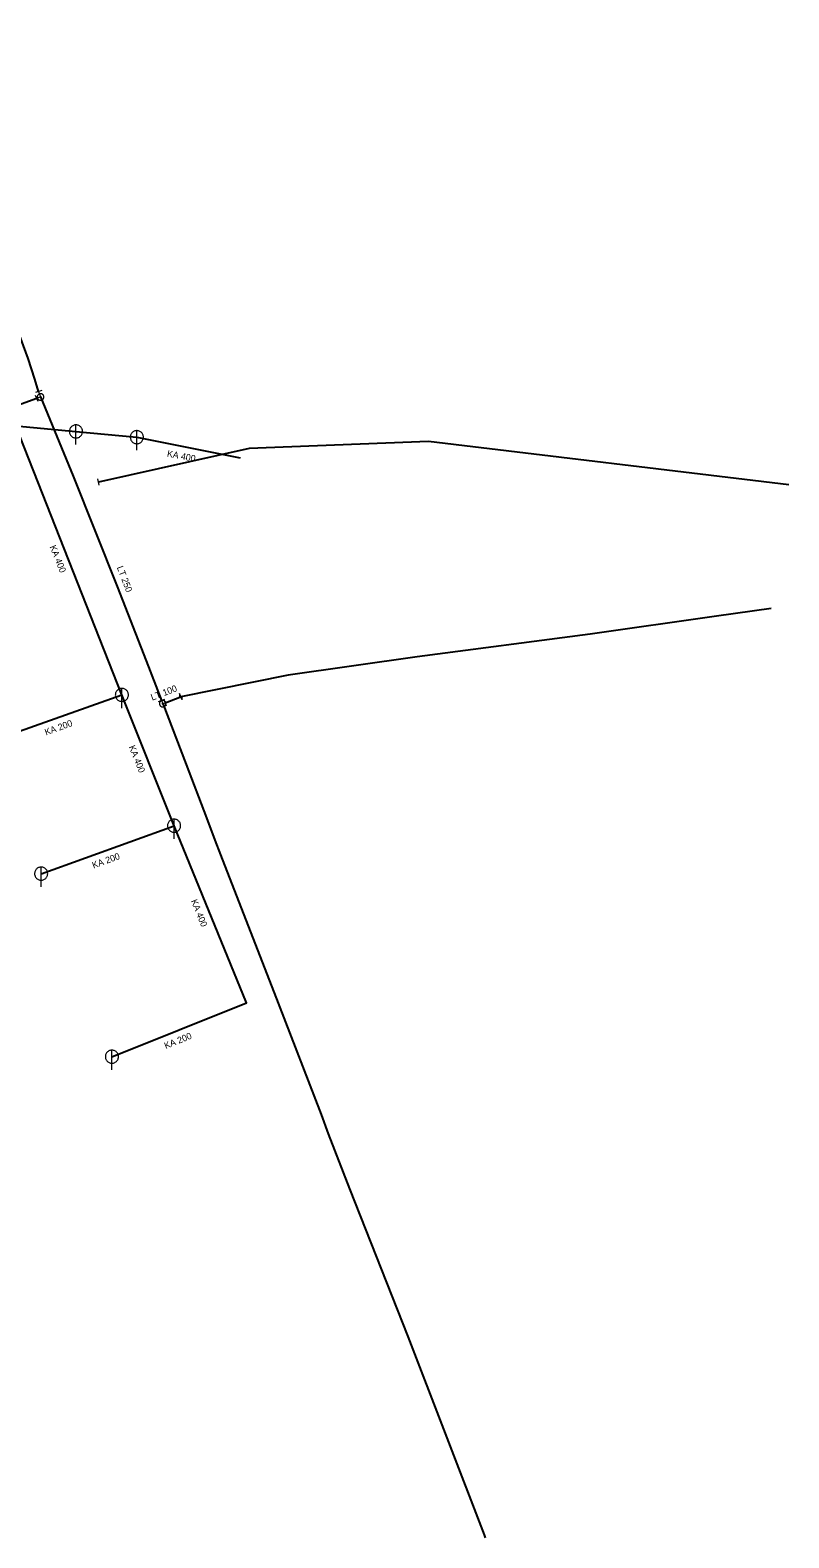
# Model space of a CAD drawing. Extents: x -690535 to -689974, y -975624 to -975325.
# Drawn here: x -690089.9 to -689974.2, y -975566.6 to -975336.7 of the extents above; entities that cross this region are included whole.
import ezdxf

# ---------------------------------------------------------------- set-up
doc = ezdxf.new("R2010")
doc.units = 0
doc.header["$LTSCALE"] = 0.4
for name, color, linetype, lineweight in [('1', 7, 'Continuous', 13), ('14', 7, 'Continuous', 25), ('17', 7, 'Continuous', 25), ('22', 7, 'Continuous', 13), ('34', 7, 'Continuous', 13), ('47', 7, 'Continuous', 13)]:
    doc.layers.add(name, color=color, linetype=linetype, lineweight=lineweight)

msp = doc.modelspace()

# ---------------------------------------------------------------- linework, layer by layer
at = {"layer": '14', "lineweight": 13}
for p, q in [((-690088.342, -975392.645), (-690088.912, -975392.874)), ((-690088.634, -975391.824), (-690088.342, -975392.645))]:
    msp.add_line(p, q, dxfattribs=at)
at = {"layer": '14'}
for p, q in [((-690092.12, -975397.03), (-690082.941, -975397.9)), ((-690082.941, -975397.9), (-690073.66, -975398.78)), ((-690073.66, -975398.78), (-690057.912, -975401.947))]:
    msp.add_line(p, q, dxfattribs=at)
for points in [[(-690094.732, -975444.739), (-690075.94, -975438.079), (-690092.12, -975397.03)], [(-690088.254, -975465.344), (-690067.978, -975458.03), (-690075.94, -975438.079)], [(-690077.458, -975493.256), (-690056.94, -975485.02), (-690067.978, -975458.03)]]:
    msp.add_lwpolyline(points, dxfattribs=at)
at = {"layer": '14', "lineweight": 13}
msp.add_lwpolyline([(-690069.916, -975438.943), (-690069.713, -975439.412), (-690069.351, -975439.267)], dxfattribs=at)
at = {"layer": '17'}
msp.add_line((-690088.912, -975392.874), (-690093.531, -975394.548), dxfattribs=at)
for points in [[(-690088.634, -975391.824), (-690089.23, -975389.914), (-690090.217, -975386.78), (-690091.866, -975382.373), (-690092.267, -975381.329), (-690094.342, -975375.603), (-690098.616, -975364.307), (-690100.726, -975358.546), (-690108.436, -975337.406), (-690108.682, -975336.702)], [(-690088.342, -975392.645), (-690083.348, -975404.702), (-690076.64, -975421.557), (-690072.237, -975432.873), (-690069.916, -975438.943)], [(-689974.23, -975406.039), (-690029.157, -975399.432), (-690056.529, -975400.526), (-690079.517, -975405.619)], [(-689976.911, -975424.893), (-689985.28, -975426.09), (-690004.51, -975428.82), (-690030.89, -975432.25), (-690050.579, -975435.05), (-690066.965, -975438.351)], [(-690069.713, -975439.412), (-690066.124, -975448.715), (-690063.059, -975456.824), (-690061.761, -975460.213), (-690060.916, -975462.471), (-690052.092, -975485.109), (-690045.574, -975502.066), (-690044.477, -975505.021), (-690041.228, -975513.396), (-690032.318, -975535.925), (-690020.684, -975566.182), (-690020.552, -975566.636)], [(-690069.351, -975439.267), (-690067.107, -975438.425), (-690066.965, -975438.351)]]:
    msp.add_lwpolyline(points, dxfattribs=at)
at = {"layer": '22'}
for p, q in [((-690082.941, -975399.9), (-690082.94, -975396.9)), ((-690073.66, -975400.78), (-690073.659, -975397.78)), ((-690075.94, -975440.079), (-690075.939, -975437.079)), ((-690067.978, -975460.03), (-690067.977, -975457.03)), ((-690088.254, -975467.344), (-690088.253, -975464.344)), ((-690077.458, -975495.256), (-690077.457, -975492.256))]:
    msp.add_line(p, q, dxfattribs=at)
for points in [[(-690081.941, -975397.9), (-690081.946, -975397.791), (-690081.964, -975397.683), (-690081.994, -975397.577), (-690082.034, -975397.476), (-690082.086, -975397.379), (-690082.148, -975397.289), (-690082.22, -975397.206), (-690082.3, -975397.132), (-690082.388, -975397.066), (-690082.482, -975397.011), (-690082.582, -975396.966), (-690082.687, -975396.933), (-690082.794, -975396.911), (-690082.903, -975396.901), (-690083.013, -975396.903), (-690083.121, -975396.917), (-690083.228, -975396.942), (-690083.331, -975396.979), (-690083.429, -975397.028), (-690083.521, -975397.086), (-690083.607, -975397.155), (-690083.684, -975397.232), (-690083.753, -975397.318), (-690083.812, -975397.41), (-690083.86, -975397.508), (-690083.897, -975397.611), (-690083.923, -975397.718), (-690083.937, -975397.826), (-690083.94, -975397.936), (-690083.93, -975398.045), (-690083.909, -975398.152), (-690083.875, -975398.256), (-690083.831, -975398.356), (-690083.776, -975398.451), (-690083.71, -975398.539), (-690083.636, -975398.619), (-690083.553, -975398.691), (-690083.463, -975398.753), (-690083.367, -975398.805), (-690083.265, -975398.846), (-690083.16, -975398.876), (-690083.052, -975398.894), (-690082.942, -975398.9), (-690082.833, -975398.894), (-690082.725, -975398.876), (-690082.62, -975398.847), (-690082.518, -975398.806), (-690082.421, -975398.754), (-690082.331, -975398.692), (-690082.248, -975398.621), (-690082.173, -975398.541), (-690082.108, -975398.453), (-690082.052, -975398.359), (-690082.008, -975398.259), (-690081.974, -975398.155), (-690081.952, -975398.047), (-690081.942, -975397.938)], [(-690072.66, -975398.78), (-690072.665, -975398.671), (-690072.683, -975398.563), (-690072.713, -975398.457), (-690072.753, -975398.356), (-690072.805, -975398.259), (-690072.867, -975398.169), (-690072.939, -975398.086), (-690073.019, -975398.012), (-690073.107, -975397.946), (-690073.201, -975397.891), (-690073.301, -975397.846), (-690073.406, -975397.813), (-690073.513, -975397.791), (-690073.622, -975397.781), (-690073.732, -975397.783), (-690073.84, -975397.797), (-690073.947, -975397.822), (-690074.05, -975397.859), (-690074.148, -975397.908), (-690074.24, -975397.966), (-690074.326, -975398.035), (-690074.403, -975398.112), (-690074.472, -975398.198), (-690074.531, -975398.29), (-690074.579, -975398.388), (-690074.616, -975398.491), (-690074.642, -975398.598), (-690074.656, -975398.706), (-690074.659, -975398.816), (-690074.649, -975398.925), (-690074.628, -975399.032), (-690074.594, -975399.136), (-690074.55, -975399.236), (-690074.495, -975399.331), (-690074.429, -975399.419), (-690074.355, -975399.499), (-690074.272, -975399.571), (-690074.182, -975399.633), (-690074.086, -975399.685), (-690073.984, -975399.726), (-690073.879, -975399.756), (-690073.771, -975399.774), (-690073.661, -975399.78), (-690073.552, -975399.774), (-690073.444, -975399.756), (-690073.339, -975399.727), (-690073.237, -975399.686), (-690073.14, -975399.634), (-690073.05, -975399.572), (-690072.967, -975399.501), (-690072.892, -975399.421), (-690072.827, -975399.333), (-690072.771, -975399.239), (-690072.727, -975399.139), (-690072.693, -975399.035), (-690072.671, -975398.927), (-690072.661, -975398.818)], [(-690074.94, -975438.079), (-690074.945, -975437.97), (-690074.963, -975437.862), (-690074.993, -975437.756), (-690075.033, -975437.655), (-690075.085, -975437.558), (-690075.147, -975437.468), (-690075.219, -975437.385), (-690075.299, -975437.311), (-690075.387, -975437.245), (-690075.481, -975437.19), (-690075.581, -975437.145), (-690075.686, -975437.112), (-690075.793, -975437.09), (-690075.902, -975437.08), (-690076.012, -975437.082), (-690076.12, -975437.096), (-690076.227, -975437.121), (-690076.33, -975437.158), (-690076.428, -975437.207), (-690076.52, -975437.265), (-690076.606, -975437.334), (-690076.683, -975437.411), (-690076.752, -975437.497), (-690076.811, -975437.589), (-690076.859, -975437.687), (-690076.896, -975437.79), (-690076.922, -975437.897), (-690076.936, -975438.005), (-690076.939, -975438.115), (-690076.929, -975438.224), (-690076.908, -975438.331), (-690076.874, -975438.435), (-690076.83, -975438.535), (-690076.775, -975438.63), (-690076.709, -975438.718), (-690076.635, -975438.798), (-690076.552, -975438.87), (-690076.462, -975438.932), (-690076.366, -975438.984), (-690076.264, -975439.025), (-690076.159, -975439.055), (-690076.051, -975439.073), (-690075.941, -975439.079), (-690075.832, -975439.073), (-690075.724, -975439.055), (-690075.619, -975439.026), (-690075.517, -975438.985), (-690075.42, -975438.933), (-690075.33, -975438.871), (-690075.247, -975438.8), (-690075.172, -975438.72), (-690075.107, -975438.632), (-690075.051, -975438.538), (-690075.007, -975438.438), (-690074.973, -975438.334), (-690074.951, -975438.226), (-690074.941, -975438.117)], [(-690066.978, -975458.03), (-690066.983, -975457.921), (-690067.001, -975457.813), (-690067.031, -975457.707), (-690067.071, -975457.606), (-690067.123, -975457.509), (-690067.185, -975457.419), (-690067.257, -975457.336), (-690067.337, -975457.262), (-690067.425, -975457.196), (-690067.519, -975457.141), (-690067.619, -975457.096), (-690067.724, -975457.063), (-690067.831, -975457.041), (-690067.94, -975457.031), (-690068.05, -975457.033), (-690068.158, -975457.047), (-690068.265, -975457.072), (-690068.368, -975457.109), (-690068.466, -975457.158), (-690068.558, -975457.216), (-690068.644, -975457.285), (-690068.721, -975457.362), (-690068.79, -975457.448), (-690068.849, -975457.54), (-690068.897, -975457.638), (-690068.934, -975457.741), (-690068.96, -975457.848), (-690068.974, -975457.956), (-690068.977, -975458.066), (-690068.967, -975458.175), (-690068.946, -975458.282), (-690068.912, -975458.386), (-690068.868, -975458.486), (-690068.813, -975458.581), (-690068.747, -975458.669), (-690068.673, -975458.749), (-690068.59, -975458.821), (-690068.5, -975458.883), (-690068.404, -975458.935), (-690068.302, -975458.976), (-690068.197, -975459.006), (-690068.089, -975459.024), (-690067.979, -975459.03), (-690067.87, -975459.024), (-690067.762, -975459.006), (-690067.657, -975458.977), (-690067.555, -975458.936), (-690067.458, -975458.884), (-690067.368, -975458.822), (-690067.285, -975458.751), (-690067.21, -975458.671), (-690067.145, -975458.583), (-690067.089, -975458.489), (-690067.045, -975458.389), (-690067.011, -975458.285), (-690066.989, -975458.177), (-690066.979, -975458.068)], [(-690087.254, -975465.344), (-690087.259, -975465.235), (-690087.277, -975465.127), (-690087.307, -975465.021), (-690087.347, -975464.92), (-690087.399, -975464.823), (-690087.461, -975464.733), (-690087.533, -975464.65), (-690087.613, -975464.576), (-690087.701, -975464.51), (-690087.795, -975464.455), (-690087.895, -975464.41), (-690088, -975464.377), (-690088.107, -975464.355), (-690088.216, -975464.345), (-690088.326, -975464.347), (-690088.434, -975464.361), (-690088.541, -975464.386), (-690088.644, -975464.423), (-690088.742, -975464.472), (-690088.834, -975464.53), (-690088.92, -975464.599), (-690088.997, -975464.676), (-690089.066, -975464.762), (-690089.125, -975464.854), (-690089.173, -975464.952), (-690089.21, -975465.055), (-690089.236, -975465.162), (-690089.25, -975465.27), (-690089.253, -975465.38), (-690089.243, -975465.489), (-690089.222, -975465.596), (-690089.188, -975465.7), (-690089.144, -975465.8), (-690089.089, -975465.895), (-690089.023, -975465.983), (-690088.949, -975466.063), (-690088.866, -975466.135), (-690088.776, -975466.197), (-690088.68, -975466.249), (-690088.578, -975466.29), (-690088.473, -975466.32), (-690088.365, -975466.338), (-690088.255, -975466.344), (-690088.146, -975466.338), (-690088.038, -975466.32), (-690087.933, -975466.291), (-690087.831, -975466.25), (-690087.734, -975466.198), (-690087.644, -975466.136), (-690087.561, -975466.065), (-690087.486, -975465.985), (-690087.421, -975465.897), (-690087.365, -975465.803), (-690087.321, -975465.703), (-690087.287, -975465.599), (-690087.265, -975465.491), (-690087.255, -975465.382)], [(-690076.458, -975493.256), (-690076.463, -975493.147), (-690076.481, -975493.039), (-690076.511, -975492.933), (-690076.551, -975492.832), (-690076.603, -975492.735), (-690076.665, -975492.645), (-690076.737, -975492.562), (-690076.817, -975492.488), (-690076.905, -975492.422), (-690076.999, -975492.367), (-690077.099, -975492.322), (-690077.204, -975492.289), (-690077.311, -975492.267), (-690077.42, -975492.257), (-690077.53, -975492.259), (-690077.638, -975492.273), (-690077.745, -975492.298), (-690077.848, -975492.335), (-690077.946, -975492.384), (-690078.038, -975492.442), (-690078.124, -975492.511), (-690078.201, -975492.588), (-690078.27, -975492.674), (-690078.329, -975492.766), (-690078.377, -975492.864), (-690078.414, -975492.967), (-690078.44, -975493.074), (-690078.454, -975493.182), (-690078.457, -975493.292), (-690078.447, -975493.401), (-690078.426, -975493.508), (-690078.392, -975493.612), (-690078.348, -975493.712), (-690078.293, -975493.807), (-690078.227, -975493.895), (-690078.153, -975493.975), (-690078.07, -975494.047), (-690077.98, -975494.109), (-690077.884, -975494.161), (-690077.782, -975494.202), (-690077.677, -975494.232), (-690077.569, -975494.25), (-690077.459, -975494.256), (-690077.35, -975494.25), (-690077.242, -975494.232), (-690077.137, -975494.203), (-690077.035, -975494.162), (-690076.938, -975494.11), (-690076.848, -975494.048), (-690076.765, -975493.977), (-690076.69, -975493.897), (-690076.625, -975493.809), (-690076.569, -975493.715), (-690076.525, -975493.615), (-690076.491, -975493.511), (-690076.469, -975493.403), (-690076.459, -975493.294)]]:
    msp.add_lwpolyline(points, close=True, dxfattribs=at)
at = {"layer": '34'}
for p, q in [((-690088.156, -975391.674), (-690089.111, -975391.972)), ((-690088.725, -975393.337), (-690089.097, -975392.409)), ((-690079.408, -975406.107), (-690079.624, -975405.13)), ((-690069.449, -975438.763), (-690070.383, -975439.121)), ((-690069.537, -975438.803), (-690069.165, -975439.731))]:
    msp.add_line(p, q, dxfattribs=at)
at = {"layer": '47'}
msp.add_line((-690066.77, -975438.821), (-690066.767, -975438.311), dxfattribs=at)
for points in [[(-690088.174, -975393.116), (-690088.126, -975393.096), (-690088.08, -975393.071), (-690088.038, -975393.041), (-690087.997, -975393.007), (-690087.961, -975392.969), (-690087.929, -975392.927), (-690087.903, -975392.883), (-690087.88, -975392.835), (-690087.862, -975392.787), (-690087.85, -975392.735), (-690087.843, -975392.683), (-690087.842, -975392.631), (-690087.846, -975392.579), (-690087.856, -975392.527), (-690087.87, -975392.477), (-690087.89, -975392.429), (-690087.915, -975392.383), (-690087.946, -975392.34), (-690087.979, -975392.3), (-690088.017, -975392.264), (-690088.059, -975392.232), (-690088.104, -975392.205), (-690088.151, -975392.182), (-690088.2, -975392.165), (-690088.251, -975392.153), (-690088.303, -975392.146), (-690088.355, -975392.144), (-690088.407, -975392.149), (-690088.459, -975392.159), (-690088.509, -975392.173), (-690088.557, -975392.193), (-690088.603, -975392.218), (-690088.647, -975392.248), (-690088.686, -975392.282), (-690088.722, -975392.32), (-690088.754, -975392.361), (-690088.782, -975392.406), (-690088.804, -975392.453), (-690088.821, -975392.503), (-690088.833, -975392.554), (-690088.84, -975392.606), (-690088.842, -975392.657), (-690088.837, -975392.71), (-690088.827, -975392.762), (-690088.813, -975392.812), (-690088.793, -975392.86), (-690088.768, -975392.906), (-690088.739, -975392.949), (-690088.704, -975392.989), (-690088.666, -975393.025), (-690088.625, -975393.057), (-690088.581, -975393.084), (-690088.533, -975393.106), (-690088.484, -975393.124), (-690088.432, -975393.136), (-690088.38, -975393.143), (-690088.329, -975393.144), (-690088.276, -975393.14), (-690088.224, -975393.13)], [(-690088.314, -975392.722), (-690088.306, -975392.719), (-690088.299, -975392.714), (-690088.292, -975392.71), (-690088.285, -975392.704), (-690088.279, -975392.698), (-690088.274, -975392.691), (-690088.269, -975392.684), (-690088.266, -975392.676), (-690088.263, -975392.668), (-690088.261, -975392.659), (-690088.26, -975392.651), (-690088.26, -975392.642), (-690088.26, -975392.634), (-690088.261, -975392.626), (-690088.264, -975392.617), (-690088.267, -975392.609), (-690088.272, -975392.602), (-690088.276, -975392.595), (-690088.282, -975392.588), (-690088.288, -975392.582), (-690088.295, -975392.577), (-690088.302, -975392.572), (-690088.31, -975392.569), (-690088.319, -975392.565), (-690088.327, -975392.564), (-690088.335, -975392.563), (-690088.344, -975392.563), (-690088.352, -975392.563), (-690088.36, -975392.564), (-690088.369, -975392.567), (-690088.377, -975392.57), (-690088.384, -975392.575), (-690088.391, -975392.579), (-690088.398, -975392.585), (-690088.404, -975392.591), (-690088.409, -975392.597), (-690088.414, -975392.605), (-690088.417, -975392.613), (-690088.421, -975392.622), (-690088.422, -975392.63), (-690088.423, -975392.638), (-690088.423, -975392.647), (-690088.423, -975392.655), (-690088.422, -975392.663), (-690088.419, -975392.672), (-690088.416, -975392.68), (-690088.411, -975392.687), (-690088.407, -975392.694), (-690088.401, -975392.701), (-690088.395, -975392.707), (-690088.389, -975392.712), (-690088.381, -975392.717), (-690088.373, -975392.72), (-690088.365, -975392.723), (-690088.356, -975392.725), (-690088.348, -975392.726), (-690088.339, -975392.726), (-690088.331, -975392.726), (-690088.323, -975392.725)], [(-690069.514, -975439.87), (-690069.467, -975439.847), (-690069.423, -975439.819), (-690069.382, -975439.786), (-690069.345, -975439.75), (-690069.311, -975439.71), (-690069.282, -975439.665), (-690069.259, -975439.619), (-690069.239, -975439.571), (-690069.225, -975439.521), (-690069.216, -975439.469), (-690069.212, -975439.416), (-690069.215, -975439.364), (-690069.222, -975439.313), (-690069.236, -975439.262), (-690069.254, -975439.213), (-690069.277, -975439.166), (-690069.305, -975439.122), (-690069.338, -975439.081), (-690069.374, -975439.044), (-690069.414, -975439.01), (-690069.459, -975438.981), (-690069.505, -975438.957), (-690069.554, -975438.937), (-690069.604, -975438.923), (-690069.655, -975438.915), (-690069.708, -975438.911), (-690069.76, -975438.913), (-690069.811, -975438.921), (-690069.862, -975438.935), (-690069.911, -975438.953), (-690069.958, -975438.976), (-690070.002, -975439.004), (-690070.044, -975439.036), (-690070.08, -975439.073), (-690070.114, -975439.113), (-690070.143, -975439.157), (-690070.168, -975439.203), (-690070.187, -975439.252), (-690070.201, -975439.303), (-690070.209, -975439.354), (-690070.213, -975439.407), (-690070.211, -975439.458), (-690070.203, -975439.51), (-690070.189, -975439.561), (-690070.171, -975439.61), (-690070.148, -975439.657), (-690070.12, -975439.701), (-690070.088, -975439.742), (-690070.051, -975439.779), (-690070.011, -975439.813), (-690069.967, -975439.842), (-690069.921, -975439.866), (-690069.873, -975439.885), (-690069.822, -975439.899), (-690069.77, -975439.908), (-690069.717, -975439.912), (-690069.666, -975439.909), (-690069.614, -975439.902), (-690069.563, -975439.888)], [(-690069.68, -975439.487), (-690069.672, -975439.483), (-690069.665, -975439.478), (-690069.659, -975439.473), (-690069.652, -975439.467), (-690069.647, -975439.46), (-690069.642, -975439.453), (-690069.638, -975439.446), (-690069.635, -975439.438), (-690069.633, -975439.429), (-690069.631, -975439.421), (-690069.631, -975439.412), (-690069.631, -975439.403), (-690069.632, -975439.395), (-690069.634, -975439.387), (-690069.637, -975439.379), (-690069.641, -975439.371), (-690069.646, -975439.364), (-690069.651, -975439.358), (-690069.657, -975439.351), (-690069.664, -975439.346), (-690069.671, -975439.341), (-690069.678, -975439.337), (-690069.686, -975439.334), (-690069.695, -975439.331), (-690069.703, -975439.33), (-690069.712, -975439.33), (-690069.721, -975439.33), (-690069.729, -975439.331), (-690069.737, -975439.333), (-690069.745, -975439.336), (-690069.753, -975439.34), (-690069.76, -975439.345), (-690069.766, -975439.35), (-690069.773, -975439.356), (-690069.778, -975439.363), (-690069.783, -975439.369), (-690069.787, -975439.377), (-690069.79, -975439.385), (-690069.793, -975439.394), (-690069.794, -975439.402), (-690069.794, -975439.411), (-690069.794, -975439.42), (-690069.793, -975439.428), (-690069.791, -975439.436), (-690069.788, -975439.444), (-690069.784, -975439.452), (-690069.779, -975439.459), (-690069.774, -975439.465), (-690069.768, -975439.472), (-690069.761, -975439.477), (-690069.755, -975439.482), (-690069.747, -975439.486), (-690069.739, -975439.489), (-690069.73, -975439.491), (-690069.722, -975439.493), (-690069.713, -975439.493), (-690069.704, -975439.493), (-690069.696, -975439.492), (-690069.688, -975439.49)]]:
    msp.add_lwpolyline(points, close=True, dxfattribs=at)
msp.add_lwpolyline([(-690066.77, -975438.821), (-690067.159, -975437.88), (-690067.162, -975438.39)], dxfattribs=at)

# ---------------------------------------------------------------- texts
at = {"layer": '1'}
for s, rotation, p in [('KA 400', 349, (-690069.117, -975401.718)), ('KA 400', 292, (-690086.976, -975415.491)), ('LT 250', 291, (-690076.728, -975418.636)), ('LT 100', 21, (-690071.311, -975438.963)), ('KA 200', 20, (-690087.5, -975444.282)), ('KA 400', 292, (-690074.914, -975446.003)), ('KA 200', 20, (-690080.264, -975464.572)), ('KA 400', 292, (-690065.432, -975469.499)), ('KA 200', 22, (-690069.242, -975492.097))]:
    msp.add_text(s, height=1, rotation=rotation, dxfattribs=at).set_placement(p)

doc.saveas('drawing.dxf')
